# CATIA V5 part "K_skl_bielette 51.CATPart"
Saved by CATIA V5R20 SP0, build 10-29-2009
Part number: skl_biellette 51
Publications: "longueur axe pivot", "liaison 51/50", "liaison 51/38 sur 51", "liaison 51/70 sur 51", "Plan.-30", "Droite.1", "Droite.2", "Droite.3", "Droite.4", "Droite.5"
Bounding box of the stored display mesh (mm): x -180 to -30, y -550 to -495, z 665 to 765
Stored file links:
  G:\Khaled_CFAO_2011\SIL\SIL_GR2\mdardier\Khaled\CAD_ThinkMOTION\K_skl_bielette 51.CATPart
  G:\Khaled_CFAO_2011\SIL\SIL_GR2\mdardier\Khaled\CAD_ThinkMOTION\K_skl_ass_tandem.CATProduct
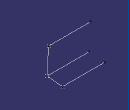
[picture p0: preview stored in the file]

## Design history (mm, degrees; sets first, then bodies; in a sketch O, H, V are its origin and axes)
External parameters (linked from other documents)
  `External.longueur axe pivot` = 150 mm
Set1
  Point1 "liaison 51/50": linked copy from another document
  Point2 "liaison 51/38 sur 51": linked copy from another document
  Point3 "liaison 51/70 sur 51": linked copy from another document
  Plane1 "Plan.-30": linked copy from another document
Set2
  Line1: type PtPt, FirstPoint Point1, SecondPoint Point2
  Line2: type PtPt, FirstPoint Point2, SecondPoint Point3
  Line3: type Normal, RefPoint Point1, RefSkin Plane1, Start 0, End 150 {= `External.longueur axe pivot`}
  Line4: type Normal, RefPoint Point2, RefSkin Plane1, Start 0, End 150 {= `External.longueur axe pivot`}
  Line5: type Normal, RefPoint Point3, RefSkin Plane1, Start 0, End 150 {= `External.longueur axe pivot`}
Body1 (main body)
